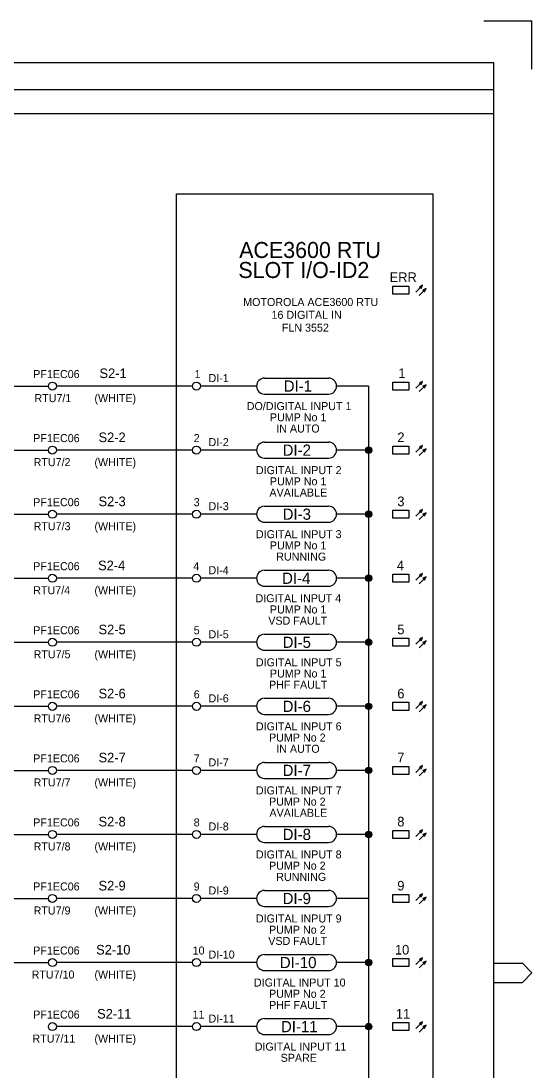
# Model space of a CAD drawing. Extents: x 0 to 841, y 0 to 594.
# Drawn here: x 681.5 to 841, y 266.1 to 594 of the extents above; entities that cross this region are included whole.
import ezdxf

# ---------------------------------------------------------------- set-up
doc = ezdxf.new("R2010")
doc.units = 0
for name, color, linetype in [('A1BORDER', 7, 'Continuous'), ('Level 1', 7, 'Continuous'), ('Level 10', 7, 'Continuous')]:
    doc.layers.add(name, color=color, linetype=linetype)

msp = doc.modelspace()

# ---------------------------------------------------------------- linework, layer by layer
at = {"layer": 'A1BORDER'}
for p, q in [((826, 594), (841, 594)), ((841, 579), (841, 594)), ((28, 581), (829, 581)), ((829, 581), (829, 15)), ((829, 299.76), (838, 299.76)), ((838, 299.76), (841, 296.76)), ((838, 293.76), (841, 296.76)), ((829, 293.76), (838, 293.76))]:
    msp.add_line(p, q, dxfattribs=at)
at = {"layer": 'Level 1'}
for p, q in [((829, 572.5), (160, 572.5)), ((829, 565), (160, 565)), ((757.5, 482.5), (777.5, 482.5)), ((512.5, 480), (690, 480)), ((735, 480), (692.5, 480)), ((755, 480), (737.5, 480)), ((790, 480), (780, 480)), ((790, 480), (790, 140)), ((757.5, 477.5), (777.5, 477.5)), ((757.5, 462.5), (777.5, 462.5)), ((475, 460), (690, 460)), ((735, 460), (692.5, 460)), ((755, 460), (737.5, 460)), ((790, 460), (780, 460)), ((757.5, 457.5), (777.5, 457.5)), ((475, 440), (690, 440)), ((735, 440), (692.5, 440)), ((755, 440), (737.5, 440)), ((757.5, 442.5), (777.5, 442.5)), ((790, 440), (780, 440)), ((757.5, 437.5), (777.5, 437.5)), ((475, 420), (690, 420)), ((735, 420), (692.5, 420)), ((755, 420), (737.5, 420)), ((757.5, 422.5), (777.5, 422.5)), ((790, 420), (780, 420)), ((757.5, 417.5), (777.5, 417.5)), ((757.5, 402.5), (777.5, 402.5)), ((475, 400), (690, 400)), ((735, 400), (692.5, 400)), ((755, 400), (737.5, 400)), ((757.5, 397.5), (777.5, 397.5)), ((790, 400), (780, 400)), ((757.5, 382.5), (777.5, 382.5)), ((512.5, 380), (690, 380)), ((735, 380), (692.5, 380)), ((755, 380), (737.5, 380)), ((757.5, 377.5), (777.5, 377.5)), ((790, 380), (780, 380)), ((757.5, 362.5), (777.5, 362.5)), ((475, 360), (690, 360)), ((735, 360), (692.5, 360)), ((755, 360), (737.5, 360)), ((757.5, 357.5), (777.5, 357.5)), ((790, 360), (780, 360)), ((757.5, 342.5), (777.5, 342.5)), ((475, 340), (690, 340)), ((735, 340), (692.5, 340)), ((755, 340), (737.5, 340)), ((790, 340), (780, 340)), ((757.5, 337.5), (777.5, 337.5)), ((757.5, 322.5), (777.5, 322.5)), ((475, 320), (690, 320)), ((735, 320), (692.5, 320)), ((755, 320), (737.5, 320)), ((790, 320), (780, 320)), ((757.5, 317.5), (777.5, 317.5)), ((757.5, 302.5), (777.5, 302.5)), ((475, 300), (690, 300)), ((735, 300), (692.5, 300)), ((755, 300), (737.5, 300)), ((790, 300), (780, 300)), ((757.5, 297.5), (777.5, 297.5)), ((757.5, 282.5), (777.5, 282.5)), ((735, 280), (692.5, 280)), ((755, 280), (737.5, 280)), ((790, 280), (780, 280)), ((757.5, 277.5), (777.5, 277.5))]:
    msp.add_line(p, q, dxfattribs=at)
for points in [[(730, 540), (810, 540), (810, 90), (730, 90)], [(797.5, 511.25), (802.5, 511.25), (802.5, 508.75), (797.5, 508.75)], [(797.5, 481.25), (802.5, 481.25), (802.5, 478.75), (797.5, 478.75)], [(797.5, 461.25), (802.5, 461.25), (802.5, 458.75), (797.5, 458.75)], [(797.5, 441.25), (802.5, 441.25), (802.5, 438.75), (797.5, 438.75)], [(797.5, 421.25), (802.5, 421.25), (802.5, 418.75), (797.5, 418.75)], [(797.5, 401.25), (802.5, 401.25), (802.5, 398.75), (797.5, 398.75)], [(797.5, 381.25), (802.5, 381.25), (802.5, 378.75), (797.5, 378.75)], [(797.5, 361.25), (802.5, 361.25), (802.5, 358.75), (797.5, 358.75)], [(797.5, 341.25), (802.5, 341.25), (802.5, 338.75), (797.5, 338.75)], [(797.5, 321.25), (802.5, 321.25), (802.5, 318.75), (797.5, 318.75)], [(797.5, 301.25), (802.5, 301.25), (802.5, 298.75), (797.5, 298.75)], [(797.5, 281.25), (802.5, 281.25), (802.5, 278.75), (797.5, 278.75)]]:
    msp.add_lwpolyline(points, close=True, dxfattribs=at)
for centre, start, end in [((757.5, 480), 90, 270), ((777.5, 480), 270, 90), ((757.5, 460), 90, 270), ((777.5, 460), 270, 90), ((757.5, 440), 90, 270), ((777.5, 440), 270, 90), ((757.5, 420), 90, 270), ((777.5, 420), 270, 90), ((757.5, 400), 90, 270), ((777.5, 400), 270, 90), ((757.5, 380), 90, 270), ((777.5, 380), 270, 90), ((757.5, 360), 90, 270), ((777.5, 360), 270, 90), ((757.5, 340), 90, 270), ((777.5, 340), 270, 90), ((757.5, 320), 90, 270), ((777.5, 320), 270, 90), ((757.5, 300), 90, 270), ((777.5, 300), 270, 90), ((757.5, 280), 90, 270), ((777.5, 280), 270, 90)]:
    msp.add_arc(centre, 2.5, start, end, dxfattribs=at)
at = {"layer": 'Level 10'}
for p, q in [((804.73, 509.36), (806.86, 511.48)), ((805.79, 508.3), (807.91, 510.42)), ((805.96, 511.07), (806.67, 511.07)), ((806, 510.93), (806.61, 510.93)), ((806.14, 510.78), (806.53, 510.78)), ((806.29, 511.23), (806.74, 511.23)), ((806.3, 510.62), (806.47, 510.62)), ((806.62, 511.38), (806.81, 511.38)), ((807.02, 510.01), (807.73, 510.01)), ((807.06, 509.87), (807.66, 509.87)), ((807.21, 509.72), (807.6, 509.72)), ((807.35, 510.17), (807.8, 510.17)), ((807.36, 509.56), (807.53, 509.56)), ((807.68, 510.31), (807.87, 510.31)), ((804.73, 479.36), (806.86, 481.48)), ((805.79, 478.3), (807.91, 480.42)), ((805.96, 481.07), (806.67, 481.07)), ((806, 480.93), (806.61, 480.93)), ((806.14, 480.78), (806.53, 480.78)), ((806.29, 481.23), (806.74, 481.23)), ((806.3, 480.62), (806.47, 480.62)), ((806.62, 481.38), (806.81, 481.38)), ((807.02, 480.01), (807.73, 480.01)), ((807.06, 479.87), (807.66, 479.87)), ((807.21, 479.72), (807.6, 479.72)), ((807.35, 480.17), (807.8, 480.17)), ((807.36, 479.56), (807.53, 479.56)), ((807.68, 480.31), (807.87, 480.31)), ((789.01, 460.1), (790.99, 460.1)), ((789.02, 459.8), (790.98, 459.8)), ((789.08, 460.4), (790.92, 460.4)), ((789.13, 459.5), (790.87, 459.5)), ((789.29, 460.7), (790.71, 460.7)), ((789.4, 459.2), (790.6, 459.2)), ((790, 461), (790, 461)), ((804.73, 459.36), (806.86, 461.48)), ((805.79, 458.3), (807.91, 460.42)), ((805.96, 461.07), (806.67, 461.07)), ((806, 460.93), (806.61, 460.93)), ((806.14, 460.78), (806.53, 460.78)), ((806.29, 461.23), (806.74, 461.23)), ((806.3, 460.62), (806.47, 460.62)), ((806.62, 461.38), (806.81, 461.38)), ((807.02, 460.01), (807.73, 460.01)), ((807.06, 459.87), (807.66, 459.87)), ((807.21, 459.72), (807.6, 459.72)), ((807.35, 460.17), (807.8, 460.17)), ((807.36, 459.56), (807.53, 459.56)), ((807.68, 460.31), (807.87, 460.31)), ((789.01, 440.1), (790.99, 440.1)), ((789.02, 439.8), (790.98, 439.8)), ((789.08, 440.4), (790.92, 440.4)), ((789.13, 439.5), (790.87, 439.5)), ((789.29, 440.7), (790.71, 440.7)), ((790, 441), (790, 441)), ((804.73, 439.36), (806.86, 441.48)), ((805.79, 438.3), (807.91, 440.42)), ((805.96, 441.07), (806.67, 441.07)), ((806, 440.93), (806.61, 440.93)), ((806.14, 440.78), (806.53, 440.78)), ((806.29, 441.23), (806.74, 441.23)), ((806.3, 440.62), (806.47, 440.62)), ((806.62, 441.38), (806.81, 441.38)), ((807.02, 440.01), (807.73, 440.01)), ((807.06, 439.87), (807.66, 439.87)), ((807.21, 439.72), (807.6, 439.72)), ((807.35, 440.17), (807.8, 440.17)), ((807.36, 439.56), (807.53, 439.56)), ((807.68, 440.31), (807.87, 440.31)), ((789.4, 439.2), (790.6, 439.2)), ((789.01, 420.1), (790.99, 420.1)), ((789.02, 419.8), (790.98, 419.8)), ((789.08, 420.4), (790.92, 420.4)), ((789.29, 420.7), (790.71, 420.7)), ((790, 421), (790, 421)), ((804.73, 419.36), (806.86, 421.48)), ((805.79, 418.3), (807.91, 420.42)), ((805.96, 421.07), (806.67, 421.07)), ((806, 420.93), (806.61, 420.93)), ((806.14, 420.78), (806.53, 420.78)), ((806.29, 421.23), (806.74, 421.23)), ((806.3, 420.62), (806.47, 420.62)), ((806.62, 421.38), (806.81, 421.38)), ((807.02, 420.01), (807.73, 420.01)), ((807.06, 419.87), (807.66, 419.87)), ((807.21, 419.72), (807.6, 419.72)), ((807.35, 420.17), (807.8, 420.17)), ((807.68, 420.31), (807.87, 420.31)), ((789.13, 419.5), (790.87, 419.5)), ((789.4, 419.2), (790.6, 419.2)), ((807.36, 419.56), (807.53, 419.56)), ((789.01, 400.1), (790.99, 400.1)), ((789.08, 400.4), (790.92, 400.4)), ((789.29, 400.7), (790.71, 400.7)), ((790, 401), (790, 401)), ((804.73, 399.36), (806.86, 401.48)), ((805.79, 398.3), (807.91, 400.42)), ((805.96, 401.07), (806.67, 401.07)), ((806, 400.93), (806.61, 400.93)), ((806.14, 400.78), (806.53, 400.78)), ((806.29, 401.23), (806.74, 401.23)), ((806.3, 400.62), (806.47, 400.62)), ((806.62, 401.38), (806.81, 401.38)), ((807.02, 400.01), (807.73, 400.01)), ((807.35, 400.17), (807.8, 400.17)), ((807.68, 400.31), (807.87, 400.31)), ((789.02, 399.8), (790.98, 399.8)), ((789.13, 399.5), (790.87, 399.5)), ((789.4, 399.2), (790.6, 399.2)), ((807.06, 399.87), (807.66, 399.87)), ((807.21, 399.72), (807.6, 399.72)), ((807.36, 399.56), (807.53, 399.56)), ((789.08, 380.4), (790.92, 380.4)), ((789.29, 380.7), (790.71, 380.7)), ((790, 381), (790, 381)), ((804.73, 379.36), (806.86, 381.48)), ((805.79, 378.3), (807.91, 380.42)), ((805.96, 381.07), (806.67, 381.07)), ((806, 380.93), (806.61, 380.93)), ((806.14, 380.78), (806.53, 380.78)), ((806.29, 381.23), (806.74, 381.23)), ((806.3, 380.62), (806.47, 380.62)), ((806.62, 381.38), (806.81, 381.38)), ((789.01, 380.1), (790.99, 380.1)), ((789.02, 379.8), (790.98, 379.8)), ((789.13, 379.5), (790.87, 379.5)), ((789.4, 379.2), (790.6, 379.2)), ((807.02, 380.01), (807.73, 380.01)), ((807.06, 379.87), (807.66, 379.87)), ((807.21, 379.72), (807.6, 379.72)), ((807.35, 380.17), (807.8, 380.17)), ((807.36, 379.56), (807.53, 379.56)), ((807.68, 380.31), (807.87, 380.31)), ((789.29, 360.7), (790.71, 360.7)), ((790, 361), (790, 361)), ((804.73, 359.36), (806.86, 361.48)), ((805.96, 361.07), (806.67, 361.07)), ((806, 360.93), (806.61, 360.93)), ((806.14, 360.78), (806.53, 360.78)), ((806.29, 361.23), (806.74, 361.23)), ((806.62, 361.38), (806.81, 361.38)), ((789.01, 360.1), (790.99, 360.1)), ((789.02, 359.8), (790.98, 359.8)), ((789.08, 360.4), (790.92, 360.4)), ((789.13, 359.5), (790.87, 359.5)), ((789.4, 359.2), (790.6, 359.2)), ((805.79, 358.3), (807.91, 360.42)), ((806.3, 360.62), (806.47, 360.62)), ((807.02, 360.01), (807.73, 360.01)), ((807.06, 359.87), (807.66, 359.87)), ((807.21, 359.72), (807.6, 359.72)), ((807.35, 360.17), (807.8, 360.17)), ((807.36, 359.56), (807.53, 359.56)), ((807.68, 360.31), (807.87, 360.31)), ((790, 341), (790, 341)), ((804.73, 339.36), (806.86, 341.48)), ((805.96, 341.07), (806.67, 341.07)), ((806.29, 341.23), (806.74, 341.23)), ((806.62, 341.38), (806.81, 341.38)), ((789.01, 340.1), (790.99, 340.1)), ((789.02, 339.8), (790.98, 339.8)), ((789.08, 340.4), (790.92, 340.4)), ((789.13, 339.5), (790.87, 339.5)), ((789.29, 340.7), (790.71, 340.7)), ((789.4, 339.2), (790.6, 339.2)), ((805.79, 338.3), (807.91, 340.42)), ((806, 340.93), (806.61, 340.93)), ((806.14, 340.78), (806.53, 340.78)), ((806.3, 340.62), (806.47, 340.62)), ((807.02, 340.01), (807.73, 340.01)), ((807.06, 339.87), (807.66, 339.87)), ((807.21, 339.72), (807.6, 339.72)), ((807.35, 340.17), (807.8, 340.17)), ((807.36, 339.56), (807.53, 339.56)), ((807.68, 340.31), (807.87, 340.31)), ((804.73, 319.36), (806.86, 321.48)), ((806.62, 321.38), (806.81, 321.38)), ((805.79, 318.3), (807.91, 320.42)), ((805.96, 321.07), (806.67, 321.07)), ((806, 320.93), (806.61, 320.93)), ((806.14, 320.78), (806.53, 320.78)), ((806.29, 321.23), (806.74, 321.23)), ((806.3, 320.62), (806.47, 320.62)), ((807.02, 320.01), (807.73, 320.01)), ((807.06, 319.87), (807.66, 319.87)), ((807.21, 319.72), (807.6, 319.72)), ((807.35, 320.17), (807.8, 320.17)), ((807.36, 319.56), (807.53, 319.56)), ((807.68, 320.31), (807.87, 320.31)), ((789.01, 300.1), (790.99, 300.1)), ((789.02, 299.8), (790.98, 299.8)), ((789.08, 300.4), (790.92, 300.4)), ((789.13, 299.5), (790.87, 299.5)), ((789.29, 300.7), (790.71, 300.7)), ((789.4, 299.2), (790.6, 299.2)), ((790, 301), (790, 301)), ((804.73, 299.36), (806.86, 301.48)), ((805.79, 298.3), (807.91, 300.42)), ((805.96, 301.07), (806.67, 301.07)), ((806, 300.93), (806.61, 300.93)), ((806.14, 300.78), (806.53, 300.78)), ((806.29, 301.23), (806.74, 301.23)), ((806.3, 300.62), (806.47, 300.62)), ((806.62, 301.38), (806.81, 301.38)), ((807.02, 300.01), (807.73, 300.01)), ((807.06, 299.87), (807.66, 299.87)), ((807.21, 299.72), (807.6, 299.72)), ((807.35, 300.17), (807.8, 300.17)), ((807.36, 299.56), (807.53, 299.56)), ((807.68, 300.31), (807.87, 300.31)), ((789.01, 280.1), (790.99, 280.1)), ((789.02, 279.8), (790.98, 279.8)), ((789.08, 280.4), (790.92, 280.4)), ((789.13, 279.5), (790.87, 279.5)), ((789.29, 280.7), (790.71, 280.7)), ((789.4, 279.2), (790.6, 279.2)), ((790, 281), (790, 281)), ((804.73, 279.36), (806.86, 281.48)), ((805.79, 278.3), (807.91, 280.42)), ((805.96, 281.07), (806.67, 281.07)), ((806, 280.93), (806.61, 280.93)), ((806.14, 280.78), (806.53, 280.78)), ((806.29, 281.23), (806.74, 281.23)), ((806.3, 280.62), (806.47, 280.62)), ((806.62, 281.38), (806.81, 281.38)), ((807.02, 280.01), (807.73, 280.01)), ((807.06, 279.87), (807.66, 279.87)), ((807.21, 279.72), (807.6, 279.72)), ((807.35, 280.17), (807.8, 280.17)), ((807.36, 279.56), (807.53, 279.56)), ((807.68, 280.31), (807.87, 280.31))]:
    msp.add_line(p, q, dxfattribs=at)
for points in [[(806.86, 511.48), (805.88, 511.04), (806.41, 510.5)], [(807.91, 510.42), (806.94, 509.98), (807.48, 509.44)], [(806.86, 481.48), (805.88, 481.04), (806.41, 480.5)], [(807.91, 480.42), (806.94, 479.98), (807.48, 479.44)], [(806.86, 461.48), (805.88, 461.04), (806.41, 460.5)], [(807.91, 460.42), (806.94, 459.98), (807.48, 459.44)], [(806.86, 441.48), (805.88, 441.04), (806.41, 440.5)], [(807.91, 440.42), (806.94, 439.98), (807.48, 439.44)], [(806.86, 421.48), (805.88, 421.04), (806.41, 420.5)], [(807.91, 420.42), (806.94, 419.98), (807.48, 419.44)], [(806.86, 401.48), (805.88, 401.04), (806.41, 400.5)], [(807.91, 400.42), (806.94, 399.98), (807.48, 399.44)], [(806.86, 381.48), (805.88, 381.04), (806.41, 380.5)], [(807.91, 380.42), (806.94, 379.98), (807.48, 379.44)], [(806.86, 361.48), (805.88, 361.04), (806.41, 360.5)], [(807.91, 360.42), (806.94, 359.98), (807.48, 359.44)], [(806.86, 341.48), (805.88, 341.04), (806.41, 340.5)], [(807.91, 340.42), (806.94, 339.98), (807.48, 339.44)], [(806.86, 321.48), (805.88, 321.04), (806.41, 320.5)], [(807.91, 320.42), (806.94, 319.98), (807.48, 319.44)], [(806.86, 301.48), (805.88, 301.04), (806.41, 300.5)], [(807.91, 300.42), (806.94, 299.98), (807.48, 299.44)], [(806.86, 281.48), (805.88, 281.04), (806.41, 280.5)], [(807.91, 280.42), (806.94, 279.98), (807.48, 279.44)]]:
    msp.add_lwpolyline(points, close=True, dxfattribs=at)
for centre, radius in [((691.25, 480), 1.25), ((736.25, 480), 1.25), ((691.25, 460), 1.25), ((736.25, 460), 1.25), ((790, 460), 1), ((691.25, 440), 1.25), ((736.25, 440), 1.25), ((790, 440), 1), ((691.25, 420), 1.25), ((736.25, 420), 1.25), ((790, 420), 1), ((691.25, 400), 1.25), ((736.25, 400), 1.25), ((790, 400), 1), ((691.25, 380), 1.25), ((736.25, 380), 1.25), ((790, 380), 1), ((691.25, 360), 1.25), ((736.25, 360), 1.25), ((790, 360), 1), ((691.25, 340), 1.25), ((736.25, 340), 1.25), ((790, 340), 1), ((691.25, 320), 1.25), ((736.25, 320), 1.25), ((691.25, 300), 1.25), ((736.25, 300), 1.25), ((790, 300), 1), ((691.25, 280), 1.25), ((736.25, 280), 1.25), ((790, 280), 1)]:
    msp.add_circle(centre, radius, dxfattribs=at)

# ---------------------------------------------------------------- texts
at = {"layer": 'Level 1'}
for s, height, p in [('ACE3600 RTU', 5, (749.58, 520)), ('SLOT I/O-ID2', 5, (749.33, 513.75)), ('ERR', 3, (796.56, 512.5)), ('MOTOROLA ACE3600 RTU', 2.5, (750.83, 505)), ('16 DIGITAL IN', 2.5, (759.67, 501)), ('FLN 3552', 2.5, (762.9, 497)), ('S2-1', 3, (705.96, 482.5)), ('1', 3, (799.25, 482.5)), ('PF1EC06', 2.5, (685.27, 482.5)), ('1', 2.5, (735.63, 482.5)), ('DI-1', 2.5, (740, 481.25)), ('DI-1', 3.5, (763.49, 478.25)), ('RTU7/1', 2.5, (685.65, 475)), ('(WHITE)', 2.5, (704.39, 475)), ('DO/DIGITAL INPUT 1', 2.5, (751.94, 472.5)), ('PUMP No 1', 2.5, (759.16, 469)), ('IN AUTO', 2.5, (761.15, 465.5)), ('PF1EC06', 2.5, (685.27, 462.5)), ('S2-2', 3, (705.67, 462.5)), ('2', 2.5, (735.38, 462.5)), ('DI-2', 2.5, (740, 461.25)), ('2', 3, (798.95, 462.5)), ('DI-2', 3.5, (763.14, 458.25)), ('RTU7/2', 2.5, (685.4, 455)), ('(WHITE)', 2.5, (704.39, 455)), ('DIGITAL INPUT 2', 2.5, (754.8, 452.5)), ('PUMP No 1', 2.5, (759.16, 449)), ('AVAILABLE', 2.5, (759.03, 445.5)), ('PF1EC06', 2.5, (685.27, 442.5)), ('S2-3', 3, (705.67, 442.5)), ('3', 2.5, (735.38, 442.5)), ('DI-3', 2.5, (740, 441.25)), ('3', 3, (798.95, 442.5)), ('DI-3', 3.5, (763.14, 438.25)), ('RTU7/3', 2.5, (685.4, 435)), ('(WHITE)', 2.5, (704.39, 435)), ('DIGITAL INPUT 3', 2.5, (754.8, 432.5)), ('PUMP No 1', 2.5, (759.16, 429)), ('RUNNING', 2.5, (761.15, 425.5)), ('PF1EC06', 2.5, (685.27, 422.5)), ('S2-4', 3, (705.52, 422.5)), ('4', 2.5, (735.25, 422.5)), ('DI-4', 2.5, (740, 421.25)), ('4', 3, (798.8, 422.5)), ('DI-4', 3.5, (762.97, 418.25)), ('RTU7/4', 2.5, (685.28, 415)), ('(WHITE)', 2.5, (704.39, 415)), ('DIGITAL INPUT 4', 2.5, (754.68, 412.5)), ('PUMP No 1', 2.5, (759.16, 409)), ('VSD FAULT', 2.5, (758.66, 405.5)), ('PF1EC06', 2.5, (685.27, 402.5)), ('S2-5', 3, (705.67, 402.5)), ('5', 2.5, (735.38, 402.5)), ('DI-5', 2.5, (740, 401.25)), ('5', 3, (798.95, 402.5)), ('DI-5', 3.5, (763.14, 398.25)), ('RTU7/5', 2.5, (685.4, 395)), ('(WHITE)', 2.5, (704.39, 395)), ('DIGITAL INPUT 5', 2.5, (754.8, 392.5)), ('PUMP No 1', 2.5, (759.16, 389)), ('PHF FAULT', 2.5, (758.91, 385.5)), ('PF1EC06', 2.5, (685.27, 382.5)), ('S2-6', 3, (705.67, 382.5)), ('6', 2.5, (735.38, 382.5)), ('DI-6', 2.5, (740, 381.25)), ('6', 3, (798.95, 382.5)), ('DI-6', 3.5, (763.14, 378.25)), ('RTU7/6', 2.5, (685.4, 375)), ('(WHITE)', 2.5, (704.39, 375)), ('DIGITAL INPUT 6', 2.5, (754.8, 372.5)), ('PUMP No 2', 2.5, (758.91, 369)), ('IN AUTO', 2.5, (761.15, 365.5)), ('PF1EC06', 2.5, (685.27, 362.5)), ('S2-7', 3, (705.67, 362.5)), ('7', 2.5, (735.38, 362.5)), ('7', 3, (798.95, 362.5)), ('DI-7', 2.5, (740, 361.25)), ('DI-7', 3.5, (763.14, 358.25)), ('RTU7/7', 2.5, (685.4, 355)), ('(WHITE)', 2.5, (704.39, 355)), ('DIGITAL INPUT 7', 2.5, (754.8, 352.5)), ('PUMP No 2', 2.5, (758.91, 349)), ('AVAILABLE', 2.5, (759.03, 345.5)), ('PF1EC06', 2.5, (685.27, 342.5)), ('S2-8', 3, (705.67, 342.5)), ('8', 2.5, (735.38, 342.5)), ('8', 3, (798.95, 342.5)), ('DI-8', 2.5, (740, 341.25)), ('DI-8', 3.5, (763.14, 338.25)), ('RTU7/8', 2.5, (685.4, 335)), ('(WHITE)', 2.5, (704.39, 335)), ('DIGITAL INPUT 8', 2.5, (754.8, 332.5)), ('PUMP No 2', 2.5, (758.91, 329)), ('RUNNING', 2.5, (761.15, 325.5)), ('PF1EC06', 2.5, (685.27, 322.5)), ('S2-9', 3, (705.67, 322.5)), ('9', 2.5, (735.38, 322.5)), ('9', 3, (798.95, 322.5)), ('DI-9', 2.5, (740, 321.25)), ('DI-9', 3.5, (763.14, 318.25)), ('RTU7/9', 2.5, (685.4, 315)), ('(WHITE)', 2.5, (704.39, 315)), ('DIGITAL INPUT 9', 2.5, (754.8, 312.5)), ('PUMP No 2', 2.5, (758.91, 309)), ('PF1EC06', 2.5, (685.27, 302.5)), ('S2-10', 3, (704.92, 302.5)), ('10', 2.5, (735.05, 302.5)), ('VSD FAULT', 2.5, (758.66, 305.5)), ('10', 3, (798.21, 302.5)), ('DI-10', 2.5, (740, 301.25)), ('DI-10', 3.5, (762.27, 298.25)), ('RTU7/10', 2.5, (684.78, 295)), ('(WHITE)', 2.5, (704.39, 295)), ('DIGITAL INPUT 10', 2.5, (754.18, 292.5)), ('PUMP No 2', 2.5, (758.91, 289)), ('S2-11', 3, (705.22, 282.5)), ('PHF FAULT', 2.5, (758.91, 285.5)), ('11', 3, (798.51, 282.5)), ('PF1EC06', 2.5, (685.27, 282.5)), ('11', 2.5, (735.01, 282.5)), ('DI-11', 2.5, (740, 281.25)), ('DI-11', 3.5, (762.62, 278.25)), ('RTU7/11', 2.5, (685.03, 275)), ('(WHITE)', 2.5, (704.39, 275)), ('DIGITAL INPUT 11', 2.5, (754.43, 272.5)), ('SPARE', 2.5, (762.52, 269))]:
    msp.add_text(s, height=height, dxfattribs=at).set_placement(p)

doc.saveas('drawing.dxf')
